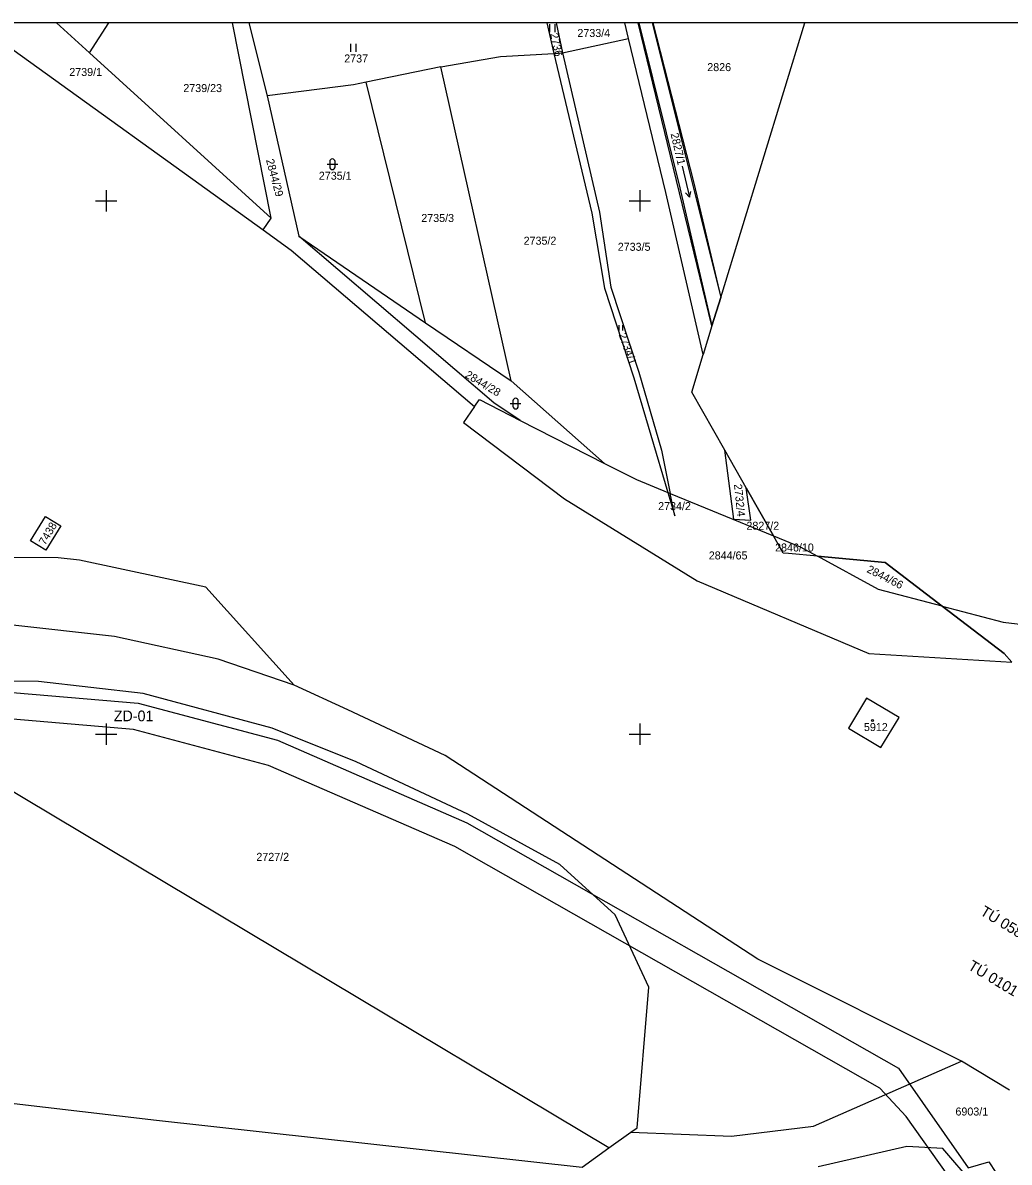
# Model space of a CAD drawing. Extents: x -800194 to -799297, y -1007177 to -1006761.
# Drawn here: x -800015.7 to -799830.8, y -1006980.2 to -1006766.6 of the extents above; entities that cross this region are included whole.
import ezdxf

# ---------------------------------------------------------------- set-up
doc = ezdxf.new("R2010")
doc.units = 0
for name, color, linetype in [('02_Osa_koleje', 7, 'Continuous'), ('Dočasné zábory', 7, 'Continuous'), ('Dočasné zábory - čísla', 7, 'Continuous'), ('Legenda 1', 7, 'Continuous'), ('Ramove udaje', 7, 'Continuous'), ('Vrstva 53', 7, 'Continuous'), ('Vrstva 55', 7, 'Continuous'), ('Vrstva 57', 7, 'Continuous'), ('Vrstva 58', 7, 'Continuous'), ('Vrstva 59', 7, 'Continuous')]:
    doc.layers.add(name, color=color, linetype=linetype)

msp = doc.modelspace()

# ---------------------------------------------------------------- linework, layer by layer
at = {"layer": 'Dočasné zábory'}
msp.add_lwpolyline([(-799842.29, -1006982.66), (-799850.11, -1006971.65), (-799855.04, -1006966.34), (-799934.68, -1006921.09), (-799969.58, -1006905.87), (-799994.89, -1006899.12), (-800033.61, -1006895.83), (-800095.58, -1006907.39), (-800120.68, -1006918.64), (-800132.21, -1006926.78), (-800163.09, -1006935.68), (-800154.78, -1006924.73), (-800136.27, -1006922.64), (-800124.59, -1006914.47), (-800095.49, -1006902.03), (-800049.12, -1006893.41), (-800033.82, -1006890.8), (-799994.03, -1006894.18), (-799967.93, -1006901.13), (-799932.44, -1006916.61), (-799851.52, -1006962.6), (-799838.48, -1006981.29), (-799834.59, -1006980.15), (-799830.67, -1006986.18)], dxfattribs=at)
at = {"layer": 'Legenda 1'}
msp.add_lwpolyline([(-800193.4, -1007176.65), (-799312.4, -1007176.65), (-799312.4, -1006766.65), (-800193.4, -1006766.65)], close=True, dxfattribs=at)
at = {"layer": 'Ramove udaje'}
for p, q in [((-800000, -1006798), (-800000, -1006802)), ((-799900, -1006798), (-799900, -1006802)), ((-800002, -1006800), (-800000, -1006800)), ((-800000, -1006800), (-799998, -1006800)), ((-799902, -1006800), (-799900, -1006800)), ((-799900, -1006800), (-799898, -1006800)), ((-800002, -1006900), (-800000, -1006900)), ((-800000, -1006898), (-800000, -1006902)), ((-800000, -1006900), (-799998, -1006900)), ((-799902, -1006900), (-799900, -1006900)), ((-799900, -1006898), (-799900, -1006902)), ((-799900, -1006900), (-799898, -1006900))]:
    msp.add_line(p, q, dxfattribs=at)
at = {"layer": 'Vrstva 53'}
for points in [[(-799973.31, -1006766.65), (-799969.88, -1006780.37), (-799963.94, -1006806.68), (-799940.15, -1006822.89), (-799924.15, -1006833.79), (-799906.63, -1006849.24), (-799900.66, -1006852.28), (-799894.78, -1006854.69), (-799894.32, -1006854.87), (-799882.56, -1006859.69), (-799879.2, -1006859.87), (-799880.09, -1006853.81), (-799874.98, -1006862.8), (-799869.94, -1006864.86), (-799866.71, -1006866.63), (-799854.06, -1006867.84), (-799843.37, -1006876), (-799831.75, -1006884.86), (-799830.3, -1006886.5)], [(-799897.71, -1006766.65), (-799884.86, -1006818.16), (-799886.49, -1006823.47), (-799900.34, -1006766.65)], [(-799830.75, -1006966.73), (-799839.73, -1006961.33), (-799877.87, -1006942.17), (-799936.47, -1006903.99), (-799954.76, -1006895.45), (-799964.79, -1006890.84), (-799981.37, -1006872.46), (-800005.05, -1006867.41), (-800009, -1006866.96), (-800038.94, -1006866.77)]]:
    msp.add_lwpolyline(points, dxfattribs=at)
at = {"layer": 'Vrstva 55'}
for p, q in [((-800024.53, -1006766.65), (-799970.63, -1006805.46)), ((-800003.16, -1006772.25), (-800009.31, -1006766.65)), ((-800003.16, -1006772.25), (-799999.51, -1006766.65)), ((-799969.12, -1006803.26), (-799976.33, -1006766.65)), ((-799973.31, -1006766.65), (-799969.88, -1006780.37)), ((-799917.43, -1006766.65), (-799916.1, -1006772.38)), ((-799915.71, -1006766.65), (-799914.5, -1006772.29)), ((-799902.13, -1006769.59), (-799902.84, -1006766.65)), ((-799884.86, -1006818.16), (-799869.08, -1006766.65)), ((-799914.5, -1006772.29), (-799902.13, -1006769.59)), ((-799895.13, -1006798.48), (-799902.13, -1006769.59)), ((-799969.12, -1006803.26), (-800003.16, -1006772.25)), ((-799916.1, -1006772.38), (-799914.5, -1006772.29)), ((-799937.29, -1006774.9), (-799951.32, -1006777.78)), ((-799924.15, -1006833.79), (-799937.29, -1006774.9)), ((-799953.68, -1006778.26), (-799969.88, -1006780.37)), ((-799951.32, -1006777.78), (-799953.68, -1006778.26)), ((-799940.15, -1006822.89), (-799951.32, -1006777.78)), ((-799969.88, -1006780.37), (-799963.94, -1006806.68)), ((-799888.13, -1006828.86), (-799895.13, -1006798.48)), ((-799970.63, -1006805.46), (-799969.12, -1006803.26)), ((-799970.63, -1006805.46), (-799965.36, -1006809.25)), ((-799963.94, -1006806.68), (-799940.15, -1006822.89)), ((-799965.36, -1006809.25), (-799930.99, -1006838.59)), ((-799886.49, -1006823.47), (-799884.86, -1006818.16)), ((-799940.15, -1006822.89), (-799924.15, -1006833.79)), ((-799886.49, -1006823.47), (-799888.13, -1006828.86)), ((-799924.15, -1006833.79), (-799906.63, -1006849.24)), ((-799922.45, -1006841.18), (-799906.63, -1006849.24)), ((-799882.39, -1006859.7), (-799884.1, -1006846.76)), ((-799880.09, -1006853.81), (-799884.1, -1006846.76)), ((-799894.78, -1006854.69), (-799894.32, -1006854.87)), ((-799894.32, -1006854.87), (-799882.56, -1006859.69)), ((-799874.98, -1006862.8), (-799880.09, -1006853.81)), ((-799882.56, -1006859.69), (-799882.39, -1006859.7)), ((-799882.56, -1006859.69), (-799874.98, -1006862.8)), ((-799905.8, -1006977.56), (-800048.34, -1006892.35)), ((-799830.75, -1006966.73), (-799839.73, -1006961.33)), ((-799905.8, -1006977.56), (-799901.69, -1006974.63)), ((-799901.69, -1006974.63), (-799882.85, -1006975.35)), ((-799910.85, -1006981.15), (-799905.8, -1006977.56))]:
    msp.add_line(p, q, dxfattribs=at)
for points in [[(-799900.21, -1006766.65), (-799892.52, -1006797.61), (-799886.49, -1006823.47)], [(-799897.57, -1006766.65), (-799889.91, -1006796.74), (-799884.86, -1006818.16)], [(-799843.37, -1006876), (-799831.92, -1006878.98), (-799822.92, -1006880.05), (-799810.74, -1006879.32), (-799788.82, -1006876.36), (-799777.45, -1006873.96), (-799762.31, -1006868.73), (-799765.35, -1006860.47), (-799748.13, -1006852.13), (-799728.87, -1006839.09), (-799711.19, -1006826.38), (-799689.75, -1006803.29), (-799676.83, -1006784.06), (-799667.97, -1006766.65)], [(-799937.29, -1006774.9), (-799926.1, -1006772.97), (-799916.1, -1006772.38)], [(-799916.1, -1006772.38), (-799909.03, -1006802.36), (-799906.63, -1006816.4), (-799901.12, -1006833.19), (-799894.78, -1006854.69)], [(-799914.5, -1006772.29), (-799907.57, -1006802.13), (-799905.43, -1006816.22), (-799900.18, -1006832.12), (-799895.95, -1006846.75), (-799894.32, -1006854.87)], [(-799922.45, -1006841.18), (-799927.36, -1006837.92), (-799963.94, -1006806.68)], [(-799884.1, -1006846.76), (-799890.29, -1006835.89), (-799888.13, -1006828.86)], [(-799930.99, -1006838.59), (-799930.09, -1006837.28), (-799922.45, -1006841.18)], [(-799930.99, -1006838.59), (-799933.07, -1006841.6), (-799914.11, -1006855.86), (-799889.24, -1006871.28), (-799857.12, -1006884.86), (-799830.3, -1006886.5)], [(-799906.63, -1006849.24), (-799900.66, -1006852.28), (-799894.78, -1006854.69)], [(-799894.78, -1006854.69), (-799893.48, -1006859.09), (-799894.32, -1006854.87)], [(-799882.39, -1006859.7), (-799879.2, -1006859.87), (-799880.09, -1006853.81)], [(-800008.55, -1006860.96), (-800011.33, -1006865.52), (-800014.19, -1006863.79), (-800011.42, -1006859.22), (-800008.55, -1006860.96)], [(-799874.98, -1006862.8), (-799869.94, -1006864.86), (-799866.71, -1006866.63)], [(-799866.71, -1006866.63), (-799872.12, -1006866.11), (-799873.12, -1006866.06), (-799874.98, -1006862.8)], [(-799964.79, -1006890.84), (-799981.37, -1006872.46), (-800005.05, -1006867.41), (-800009, -1006866.96), (-800038.94, -1006866.77), (-800041.43, -1006865.34), (-800043.88, -1006869.49), (-800044.4, -1006869.18), (-800042.89, -1006866.63)], [(-799843.37, -1006876), (-799855.29, -1006872.89), (-799866.71, -1006866.63)], [(-799843.37, -1006876), (-799854.06, -1006867.84), (-799866.71, -1006866.63)], [(-799830.3, -1006886.5), (-799831.75, -1006884.86), (-799843.37, -1006876)], [(-799964.79, -1006890.84), (-799979.01, -1006885.96), (-799998.45, -1006881.67), (-800018.08, -1006879.48), (-800038.51, -1006879.76), (-800056.43, -1006881.95), (-800070.76, -1006884.38), (-800080.47, -1006886.59), (-800089.79, -1006889.63), (-800088.91, -1006893.34), (-800105.12, -1006899.41), (-800124.67, -1006911.59), (-800137.62, -1006920.11), (-800154.3, -1006934.53), (-800165.04, -1006947.7)], [(-799901.69, -1006974.63), (-799900.54, -1006973.82), (-799898.31, -1006947.43), (-799904.63, -1006933.89), (-799915, -1006924.46), (-799932.22, -1006915.03), (-799953.17, -1006905.18), (-799968.93, -1006898.86), (-799993.08, -1006892.39), (-800012.71, -1006890.11), (-800033.89, -1006890), (-800048.34, -1006892.35)], [(-799839.73, -1006961.33), (-799877.87, -1006942.17), (-799936.47, -1006903.99), (-799954.76, -1006895.45), (-799964.79, -1006890.84)], [(-799851.43, -1006896.91), (-799857.54, -1006893.23), (-799860.93, -1006898.86), (-799854.86, -1006902.52), (-799851.43, -1006896.91)], [(-800126.38, -1006954.46), (-800114.82, -1006956.57), (-800087.75, -1006960.99), (-799990.59, -1006972.38), (-799910.85, -1006981.15)], [(-799882.85, -1006975.35), (-799867.48, -1006973.49), (-799839.73, -1006961.33)], [(-799831.14, -1007046.62), (-799837.54, -1006984.31), (-799843.2, -1006977.69), (-799849.98, -1006977.29), (-799866.6, -1006981.12)]]:
    msp.add_lwpolyline(points, dxfattribs=at)
at = {"layer": 'Vrstva 58'}
for p, q in [((-799916.86, -1006768.43), (-799916.86, -1006766.93)), ((-799915.86, -1006768.43), (-799915.86, -1006766.93)), ((-799954.2, -1006772.07), (-799954.2, -1006770.57)), ((-799953.2, -1006772.07), (-799953.2, -1006770.57)), ((-799958.64, -1006793.17), (-799956.64, -1006793.17)), ((-799958.14, -1006792.67), (-799958.14, -1006793.67)), ((-799957.14, -1006793.67), (-799957.14, -1006792.67)), ((-799892.08, -1006793.51), (-799890.73, -1006799.35)), ((-799890.73, -1006799.35), (-799891.44, -1006798.51)), ((-799890.73, -1006799.35), (-799890.46, -1006798.29)), ((-799903.86, -1006824.36), (-799903.86, -1006823.35)), ((-799903.19, -1006824.36), (-799903.19, -1006823.35)), ((-799924.3, -1006838.04), (-799922.3, -1006838.04)), ((-799923.8, -1006837.54), (-799923.8, -1006838.54)), ((-799922.8, -1006838.54), (-799922.8, -1006837.54))]:
    msp.add_line(p, q, dxfattribs=at)
for centre, start, end in [((-799957.64, -1006792.67), 0, 180), ((-799957.64, -1006793.67), 180, 359.9879), ((-799923.3, -1006837.54), 0, 180), ((-799923.3, -1006838.54), 180, 359.9879)]:
    msp.add_arc(centre, 0.5, start, end, dxfattribs=at)
at = {"layer": 'Vrstva 59'}
msp.add_circle((-799856.4, -1006897.43), 0.175, dxfattribs=at)

# ---------------------------------------------------------------- texts
at = {"layer": '02_Osa_koleje'}
for s, rotation, p in [('TÚ 0581 - směr Žatec', 328.6802, (-799836.39, -1006933.75)), ('TÚ 0101 - směr Žatec', 328.939, (-799838.66, -1006943.96))]:
    msp.add_text(s, height=2, rotation=rotation, dxfattribs=at).set_placement(p)
at = {"layer": 'Dočasné zábory - čísla'}
msp.add_text('ZD-01', height=2, rotation=0, dxfattribs=at).set_placement((-799998.6, -1006897.58))
at = {"layer": 'Vrstva 57'}
for s, rotation, p in [('2736', 282, (-799916.82, -1006768.71)), ('2827/1', 283, (-799894.26, -1006787.46)), ('2844/29', 285, (-799970.09, -1006792.38)), ('2734/1', 289.2956, (-799904, -1006825.1)), ('2844/28', 329, (-799932.89, -1006833.03)), ('2732/4', 276, (-799882.37, -1006853.18)), ('7438', 59, (-800011.47, -1006864.68)), ('2844/66', 333, (-799857.61, -1006869.57))]:
    msp.add_text(s, height=1.5, rotation=rotation, dxfattribs=at).set_placement(p)
for s, p in [('2733/4', (-799911.71, -1006769.31)), ('2737', (-799955.41, -1006774.09)), ('2739/1', (-800006.94, -1006776.62)), ('2826', (-799887.37, -1006775.71)), ('2739/23', (-799985.57, -1006779.64)), ('2735/1', (-799960.17, -1006796.07)), ('2735/3', (-799940.97, -1006803.99)), ('2735/2', (-799921.79, -1006808.25)), ('2733/5', (-799904.15, -1006809.39)), ('2734/2', (-799896.58, -1006858)), ('2827/2', (-799880.03, -1006861.68)), ('2844/65', (-799887.09, -1006867.25)), ('2846/10', (-799874.66, -1006865.76)), ('5912', (-799858.01, -1006899.42)), ('2727/2', (-799971.88, -1006923.75)), ('6903/1', (-799840.86, -1006971.49))]:
    msp.add_text(s, height=1.5, dxfattribs=at).set_placement(p)

doc.saveas('drawing.dxf')
